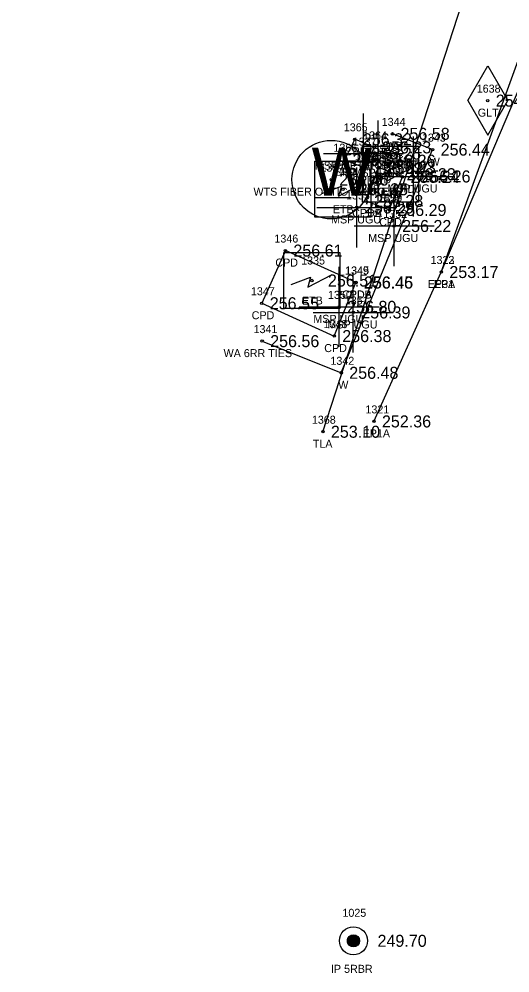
# Model space of a CAD drawing. Extents: x 1961231 to 1962574, y 799865 to 801120.
# Drawn here: x 1961948.3 to 1962009.5, y 800349.4 to 800468.6 of the extents above; entities that cross this region are included whole.
import ezdxf

# ---------------------------------------------------------------- set-up
doc = ezdxf.new("R2010")
doc.units = 0
for name, color, linetype in [('RD_EX_BldgApp', 7, 'Continuous'), ('RD_EX_Conc', 7, 'Continuous'), ('RD_EX_Conc_txCode', 7, 'Continuous'), ('RD_EX_DV_Prop_txCode', 7, 'Continuous'), ('RD_EX_DV_PropPin', 7, 'Continuous'), ('RD_EX_Misc', 7, 'Continuous'), ('RD_EX_Misc_txCode', 7, 'Continuous'), ('RD_EX_Road', 7, 'Continuous'), ('RD_EX_Road_txCode', 7, 'Continuous'), ('RD_EX_TX_Conc_ELEV', 7, 'Continuous'), ('RD_EX_TX_DV_Prop_ELEV', 7, 'Continuous'), ('RD_EX_TX_Misc_ELEV', 7, 'Continuous'), ('RD_EX_TX_Road_ELEV', 7, 'Continuous'), ('RD_EX_TX_UT_ELEV', 7, 'Continuous'), ('RD_EX_TX_VEG_ELEV', 7, 'Continuous'), ('RD_EX_UT', 7, 'Continuous'), ('RD_EX_UT_txCode', 7, 'Continuous'), ('RD_EX_VEG', 7, 'Continuous'), ('RD_EX_VEG_txCode', 7, 'Continuous'), ('RD_SMD_Locator', 7, 'Continuous')]:
    doc.layers.add(name, color=color, linetype=linetype)

msp = doc.modelspace()

# ---------------------------------------------------------------- linework, layer by layer
at = {"layer": 'RD_EX_BldgApp'}
msp.add_lwpolyline([(1961978.58, 800428.37), (1961988.45, 800424.41), (1961999.86, 800452.29), (1961994.85, 800454.26)], dxfattribs=at)
at = {"layer": 'RD_EX_Conc'}
for points in [[(1961991.53, 800449.98), (1961992.55, 800452.57), (1961990.14, 800453.58), (1961988.87, 800451.03), (1961991.53, 800449.98)], [(1961991.55, 800445.88), (1961994.45, 800444.75), (1961996.09, 800448.89), (1961993.12, 800450.06), (1961991.55, 800445.88)], [(1961990.3, 800435.7), (1961981.48, 800439.68), (1961978.53, 800433.1), (1961987.58, 800429), (1961990.27, 800435.68)]]:
    msp.add_lwpolyline(points, dxfattribs=at)
at = {"layer": 'RD_EX_DV_PropPin'}
for p, q in [((1961989.53, 800352.85), (1961989.53, 800354.07)), ((1961989.56, 800352.83), (1961989.56, 800354.1)), ((1961989.6, 800352.81), (1961989.6, 800354.12)), ((1961989.63, 800352.79), (1961989.63, 800354.14)), ((1961989.67, 800352.77), (1961989.67, 800354.16)), ((1961989.7, 800352.76), (1961989.7, 800354.17)), ((1961989.74, 800352.74), (1961989.74, 800354.18)), ((1961989.77, 800352.73), (1961989.77, 800354.2)), ((1961989.81, 800352.72), (1961989.81, 800354.2)), ((1961989.84, 800352.72), (1961989.84, 800354.21)), ((1961989.88, 800352.71), (1961989.88, 800354.22)), ((1961989.91, 800352.71), (1961989.91, 800354.22)), ((1961989.95, 800352.7), (1961989.95, 800354.22)), ((1961989.98, 800352.7), (1961989.98, 800354.22)), ((1961990.02, 800352.7), (1961990.02, 800354.22)), ((1961990.05, 800352.71), (1961990.05, 800354.22)), ((1961990.09, 800352.71), (1961990.09, 800354.22)), ((1961990.12, 800352.72), (1961990.12, 800354.21)), ((1961990.16, 800352.72), (1961990.16, 800354.2)), ((1961990.19, 800352.73), (1961990.19, 800354.2)), ((1961990.23, 800352.74), (1961990.23, 800354.18)), ((1961990.26, 800352.76), (1961990.26, 800354.17)), ((1961990.3, 800352.77), (1961990.3, 800354.16)), ((1961990.33, 800352.79), (1961990.33, 800354.14)), ((1961990.37, 800352.81), (1961990.37, 800354.12)), ((1961990.4, 800352.83), (1961990.4, 800354.1)), ((1961990.44, 800352.85), (1961990.44, 800354.07)), ((1961989.25, 800353.27), (1961989.25, 800353.66)), ((1961989.28, 800353.17), (1961989.28, 800353.76)), ((1961989.32, 800353.09), (1961989.32, 800353.83)), ((1961989.35, 800353.04), (1961989.35, 800353.89)), ((1961989.39, 800352.99), (1961989.39, 800353.94)), ((1961989.42, 800352.95), (1961989.42, 800353.98)), ((1961989.46, 800352.91), (1961989.46, 800354.01)), ((1961989.49, 800352.88), (1961989.49, 800354.05)), ((1961990.47, 800352.88), (1961990.47, 800354.05)), ((1961990.51, 800352.91), (1961990.51, 800354.01)), ((1961990.54, 800352.95), (1961990.54, 800353.98)), ((1961990.58, 800352.99), (1961990.58, 800353.94)), ((1961990.61, 800353.04), (1961990.61, 800353.89)), ((1961990.65, 800353.09), (1961990.65, 800353.83)), ((1961990.68, 800353.17), (1961990.68, 800353.76)), ((1961990.72, 800353.27), (1961990.72, 800353.66))]:
    msp.add_line(p, q, dxfattribs=at)
for radius in [1.75, 0.761]:
    msp.add_circle((1961989.98, 800353.46), radius, dxfattribs=at)
at = {"layer": 'RD_EX_Misc'}
for p, q in [((1961991.24, 800446.79), (1961991.24, 800456.79)), ((1961993.08, 800445.91), (1961993.08, 800455.91)), ((1961997.45, 800443.94), (1961997.45, 800453.94)), ((1961986.24, 800451.79), (1961996.24, 800451.79)), ((1961988.08, 800450.91), (1961998.08, 800450.91)), ((1961990.4, 800440.07), (1961990.4, 800450.07)), ((1961992.45, 800448.94), (1962002.45, 800448.94)), ((1961995.05, 800437.75), (1961995.05, 800447.75)), ((1961985.4, 800445.07), (1961995.4, 800445.07)), ((1961990.05, 800442.75), (1962000.05, 800442.75)), ((1961988.19, 800427.65), (1961988.19, 800437.65)), ((1961989.95, 800426.95), (1961989.95, 800436.95)), ((1961983.19, 800432.65), (1961993.19, 800432.65)), ((1961984.95, 800431.95), (1961994.95, 800431.95))]:
    msp.add_line(p, q, dxfattribs=at)
at = {"layer": 'RD_EX_Road'}
for points in [[(1961992.53, 800418.34), (1962000.94, 800437), (1962011.01, 800464.81), (1962016.84, 800481.64), (1962015.31, 800499.65), (1961996.99, 800516.71), (1961979.47, 800530.76), (1961969.8, 800538.75), (1961958.28, 800547.16), (1961941.07, 800560.82), (1961925.41, 800573.41), (1961918.19, 800579.25), (1961879.32, 800611.18), (1961866.07, 800621.08), (1961838.29, 800653.43)], [(1962000.94, 800437), (1962012.34, 800463.86), (1962019.24, 800480.8), (1962017.64, 800497.35), (1962015.31, 800499.65)]]:
    msp.add_lwpolyline(points, dxfattribs=at)
at = {"layer": 'RD_EX_UT'}
for p, q in [((1962004.23, 800458.41), (1962006.73, 800462.74)), ((1962006.73, 800462.74), (1962009.23, 800458.41)), ((1962004.23, 800458.41), (1962006.73, 800454.08)), ((1962006.73, 800454.08), (1962009.23, 800458.41)), ((1961985.08, 800446.33), (1961989.71, 800446.33))]:
    msp.add_line(p, q, dxfattribs=at)
for points in [[(1961991.11, 800445.72), (1961991.11, 800452.72), (1961998.11, 800452.72), (1961998.11, 800445.72)], [(1961985.15, 800443.84), (1961985.15, 800450.84), (1961992.15, 800450.84), (1961992.15, 800443.84)], [(1961981.29, 800432.44), (1961981.29, 800439.44), (1961988.29, 800439.44), (1961988.29, 800432.44)]]:
    msp.add_lwpolyline(points, close=True, dxfattribs=at)
for points in [[(1961992.01, 800448.71), (1961994.43, 800449.61), (1961994.08, 800448.37), (1961997.13, 800449.96)], [(1961986.05, 800446.83), (1961988.47, 800447.73), (1961988.13, 800446.49), (1961991.17, 800448.08)], [(1961982.19, 800435.44), (1961984.62, 800436.34), (1961984.27, 800435.09), (1961987.31, 800436.68)]]:
    msp.add_lwpolyline(points, dxfattribs=at)
msp.add_circle((1961987.21, 800448.54), 4.91, dxfattribs=at)
at = {"layer": 'RD_EX_VEG'}
msp.add_lwpolyline([(1961986.16, 800417.05), (1962008.73, 800486.69), (1961986.14, 800509.28), (1961949.4, 800540.42), (1961909.42, 800571.42), (1961867.44, 800598.73), (1961825.04, 800634.78), (1961788.24, 800662.23), (1961745.49, 800697.38)], dxfattribs=at)
at = {"layer": 'RD_SMD_Locator'}
for centre in [(1962006.73, 800458.41), (1961994.85, 800454.26), (1961990.14, 800453.58), (1961991.24, 800451.79), (1961992.55, 800452.57), (1961999.86, 800452.29), (1961988.87, 800451.03), (1961993.08, 800450.91), (1961991.53, 800449.98), (1961991.53, 800449.98), (1961993.12, 800450.06), (1961994.61, 800449.22), (1961987.21, 800448.54), (1961996.09, 800448.89), (1961997.45, 800448.94), (1961988.65, 800447.34), (1961991.55, 800445.88), (1961991.55, 800445.88), (1961990.4, 800445.07), (1961994.45, 800444.75), (1961995.05, 800442.75), (1961981.48, 800439.68), (1962000.94, 800437), (1962000.94, 800437), (1961984.79, 800435.94), (1961990.27, 800435.68), (1961990.3, 800435.7), (1961978.53, 800433.1), (1961988.19, 800432.65), (1961989.95, 800431.95), (1961987.58, 800429), (1961978.58, 800428.37), (1961988.45, 800424.41), (1961992.53, 800418.34), (1961986.16, 800417.05), (1961989.98, 800353.46)]:
    msp.add_circle(centre, 0.15, dxfattribs=at)

# ---------------------------------------------------------------- texts
at = {"layer": 'RD_EX_Conc_txCode'}
for s, p in [('1365', (1961988.77, 800454.58)), ('1364', (1961991.18, 800453.57)), ('1366', (1961987.47, 800452.03)), ('CPD', (1961988.89, 800451.58)), ('1363', (1961990.16, 800450.98)), ('1367', (1961990.16, 800450.98)), ('1361', (1961992.04, 800451.06)), ('CPD', (1961991.3, 800450.57)), ('1360', (1961994.68, 800449.89)), ('CPD', (1961987.61, 800449.03)), ('CPDA', (1961989.79, 800447.98)), ('CPDB', (1961989.8, 800447.98)), ('CPD', (1961991.87, 800448.06)), ('1362', (1961990.18, 800446.88)), ('1358', (1961990.2, 800446.88)), ('CPD', (1961994.84, 800446.89)), ('1359', (1961993.1, 800445.75)), ('CPDA', (1961989.81, 800443.88)), ('CPDB', (1961989.82, 800443.88)), ('CPD', (1961993.19, 800442.75)), ('1346', (1961980.11, 800440.68)), ('CPD', (1961980.23, 800437.68)), ('1349', (1961988.92, 800436.68)), ('1345', (1961988.95, 800436.7)), ('1347', (1961977.18, 800434.1)), ('CPDB', (1961988.54, 800433.68)), ('CPDA', (1961988.56, 800433.7)), ('CPD', (1961977.28, 800431.1)), ('1348', (1961986.24, 800430)), ('CPD', (1961986.33, 800427))]:
    msp.add_text(s, height=1, dxfattribs=at).set_placement(p)
at = {"layer": 'RD_EX_DV_Prop_txCode'}
for s, p in [('1025', (1961988.6, 800356.46)), ('IP 5RBR', (1961987.17, 800349.46))]:
    msp.add_text(s, height=1, dxfattribs=at).set_placement(p)
at = {"layer": 'RD_EX_Misc_txCode'}
for s, p in [('1344', (1961993.5, 800455.26)), ('1343', (1961998.52, 800453.29)), ('1337', (1961989.89, 800452.79)), ('WB', (1961994.01, 800452.26)), ('1354', (1961991.74, 800451.91)), ('MSP METER BOX', (1961985.15, 800449.79)), ('1353', (1961996.1, 800449.94)), ('W', (1961999.49, 800450.29)), ('MSP UGU', (1961989.86, 800448.91)), ('1355', (1961989.05, 800446.07)), ('MSP UGU', (1961994.23, 800446.94)), ('1352', (1961993.7, 800443.75)), ('MSP UGU', (1961987.18, 800443.07)), ('MSP UGU', (1961991.82, 800440.75)), ('1350', (1961986.8, 800433.65)), ('1351', (1961988.89, 800432.95)), ('MSP UGU', (1961984.97, 800430.65)), ('1341', (1961977.51, 800429.37)), ('MSP UGU', (1961986.73, 800429.95)), ('WA 6RR TIES', (1961973.77, 800426.37)), ('1342', (1961987.1, 800425.41)), ('W', (1961988.08, 800422.41))]:
    msp.add_text(s, height=1, dxfattribs=at).set_placement(p)
at = {"layer": 'RD_EX_Road_txCode'}
for s, p in [('1322', (1961999.6, 800438)), ('1323', (1961999.6, 800438)), ('EP3A', (1961999.25, 800435)), ('EP1', (1962000.02, 800435)), ('1321', (1961991.47, 800419.34)), ('EP1A', (1961991.12, 800416.34))]:
    msp.add_text(s, height=1, dxfattribs=at).set_placement(p)
at = {"layer": 'RD_EX_TX_Conc_ELEV'}
for s, p in [('256.32', (1961991.14, 800452.83)), ('256.23', (1961993.55, 800451.82)), ('256.32', (1961989.87, 800450.28)), ('256.22', (1961992.53, 800449.23)), ('256.22', (1961992.53, 800449.23)), ('256.23', (1961994.12, 800449.31)), ('256.24', (1961997.09, 800448.14)), ('256.28', (1961992.55, 800445.13)), ('256.28', (1961992.55, 800445.13)), ('256.29', (1961995.45, 800444)), ('256.61', (1961982.48, 800438.93)), ('256.46', (1961991.27, 800434.93)), ('256.45', (1961991.3, 800434.95)), ('256.55', (1961979.53, 800432.35)), ('256.38', (1961988.58, 800428.25))]:
    msp.add_text(s, height=1.5, dxfattribs=at).set_placement(p)
at = {"layer": 'RD_EX_TX_DV_Prop_ELEV'}
msp.add_text('249.70', height=1.5, dxfattribs=at).set_placement((1961992.98, 800352.71))
at = {"layer": 'RD_EX_TX_Misc_ELEV'}
for s, p in [('256.58', (1961995.85, 800453.51)), ('256.44', (1962000.86, 800451.54)), ('256.26', (1961992.24, 800451.04)), ('256.26', (1961994.08, 800450.16)), ('256.26', (1961998.45, 800448.19)), ('256.29', (1961991.4, 800444.32)), ('256.22', (1961996.05, 800442)), ('256.80', (1961989.19, 800431.9)), ('256.39', (1961990.95, 800431.2)), ('256.56', (1961979.58, 800427.62)), ('256.48', (1961989.45, 800423.66))]:
    msp.add_text(s, height=1.5, dxfattribs=at).set_placement(p)
at = {"layer": 'RD_EX_TX_Road_ELEV'}
for s, p in [('253.17', (1962001.94, 800436.25)), ('253.17', (1962001.94, 800436.25)), ('252.36', (1961993.53, 800417.59))]:
    msp.add_text(s, height=1.5, dxfattribs=at).set_placement(p)
at = {"layer": 'RD_EX_TX_UT_ELEV'}
for s, p in [('254.64', (1962007.73, 800457.66)), ('256.23', (1961996.61, 800448.47)), ('256.46', (1961988.21, 800447.79)), ('256.35', (1961990.65, 800446.59)), ('256.51', (1961986.79, 800435.19))]:
    msp.add_text(s, height=1.5, dxfattribs=at).set_placement(p)
at = {"layer": 'RD_EX_TX_VEG_ELEV'}
msp.add_text('253.10', height=1.5, dxfattribs=at).set_placement((1961987.16, 800416.3))
at = {"layer": 'RD_EX_UT'}
msp.add_text('W', height=6, dxfattribs=at).set_placement((1961984.75, 800446.54))
at = {"layer": 'RD_EX_UT_txCode'}
for s, p in [('1638', (1962005.36, 800459.41)), ('GLT', (1962005.49, 800456.41)), ('1336', (1961993.24, 800451.22)), ('1357', (1961985.86, 800449.54)), ('1356', (1961987.28, 800449.34)), ('WTS FIBER OPTIC MARKER', (1961977.5, 800446.54)), ('ETB', (1961993.36, 800446.22)), ('ETB', (1961987.41, 800444.34)), ('1335', (1961983.45, 800437.94)), ('ETB', (1961983.55, 800432.94))]:
    msp.add_text(s, height=1, dxfattribs=at).set_placement(p)
at = {"layer": 'RD_EX_VEG_txCode'}
for s, p in [('1368', (1961984.79, 800418.05)), ('TLA', (1961984.9, 800415.05))]:
    msp.add_text(s, height=1, dxfattribs=at).set_placement(p)

doc.saveas('drawing.dxf')
